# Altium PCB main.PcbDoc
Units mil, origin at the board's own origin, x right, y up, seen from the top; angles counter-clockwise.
Board outline 2845.7 x 1927.04 mil, 2 copper layers (Top Layer, Bottom Layer); 12 components, 7 nets, 37 pads, 138 vias.
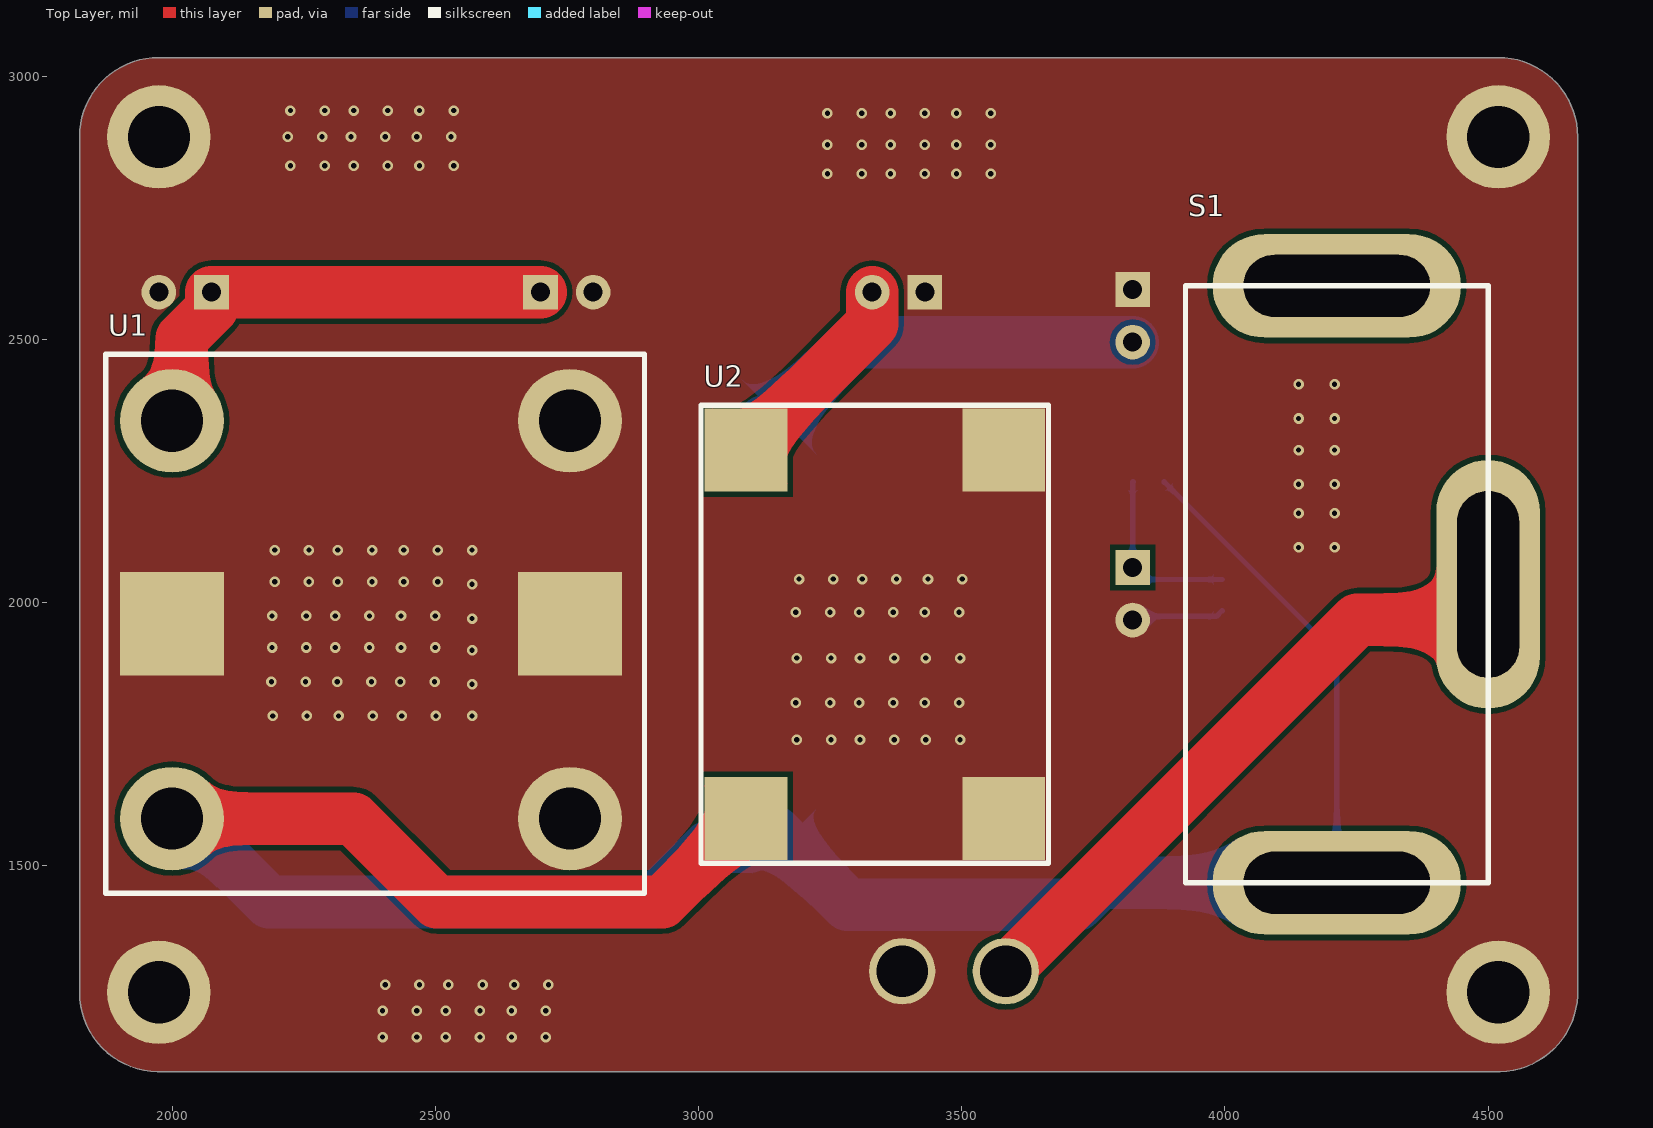
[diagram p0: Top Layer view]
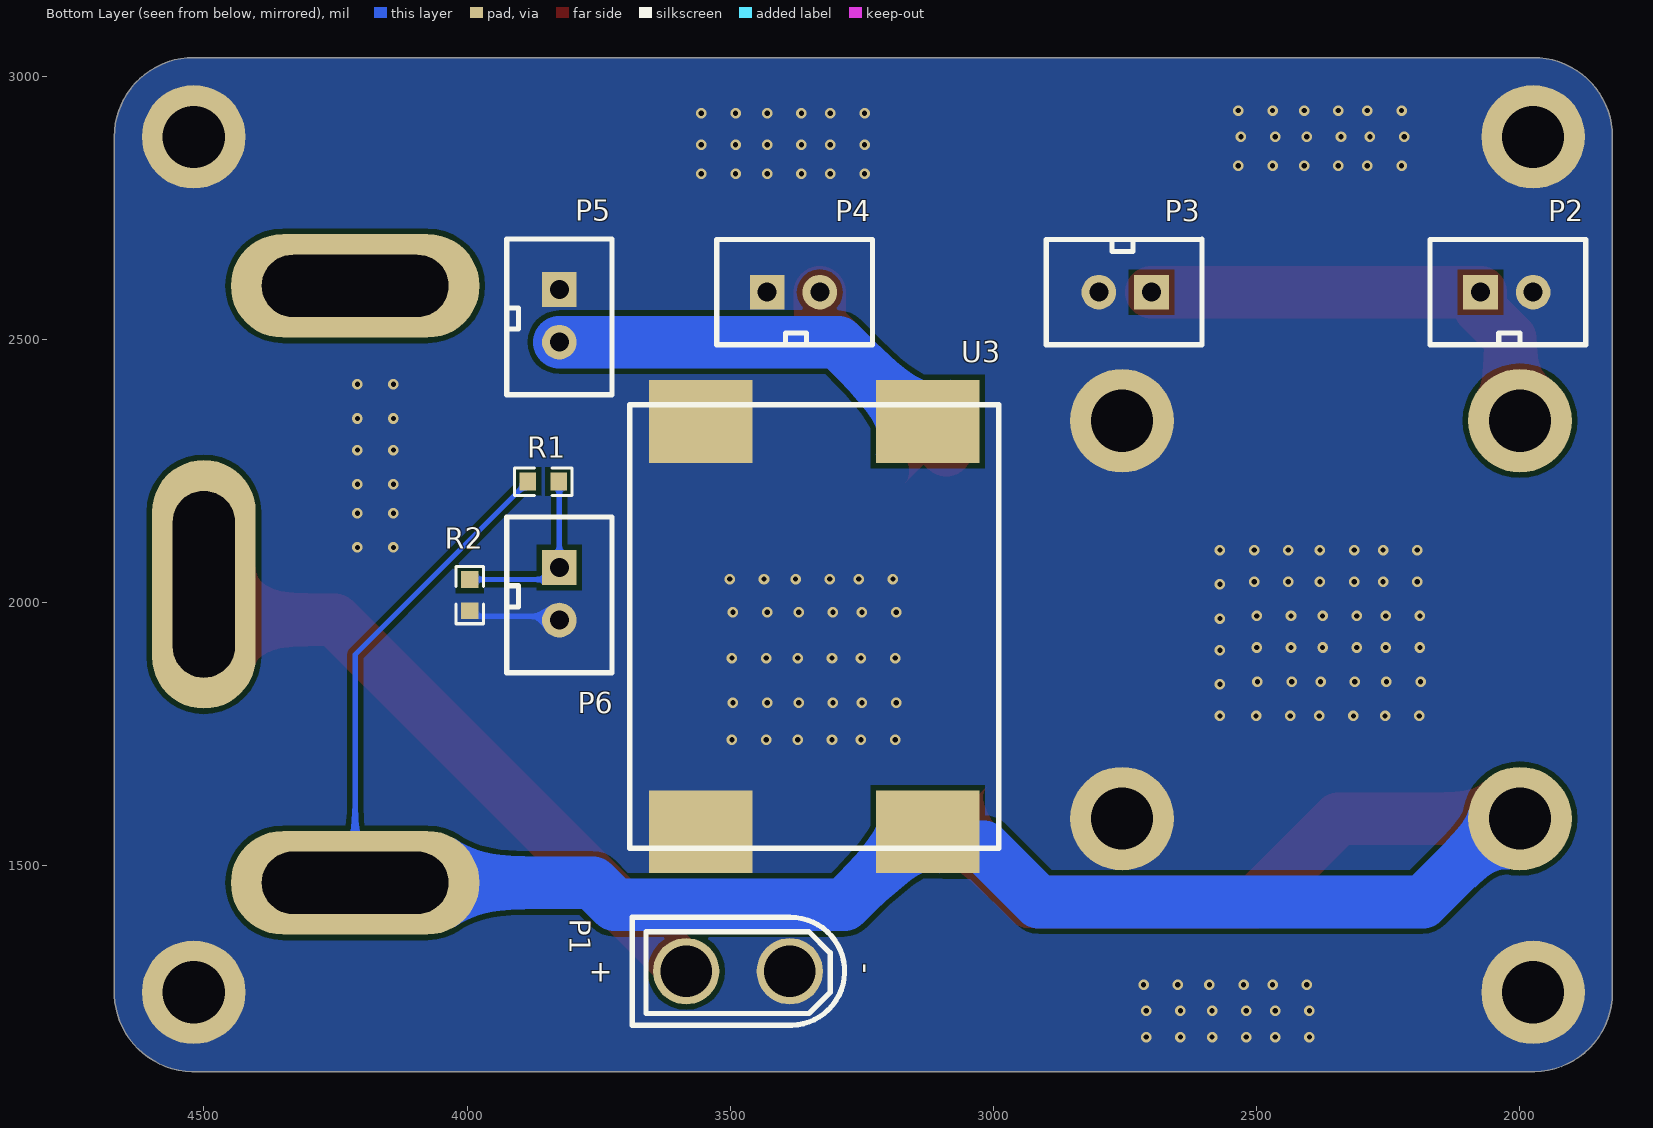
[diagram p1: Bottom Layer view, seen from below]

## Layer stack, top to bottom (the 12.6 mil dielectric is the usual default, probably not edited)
Top Solder: solder mask 0.4, Solder Resist, Dk 3.5
Top Layer: signal copper 1.4
Dielectric 1: dielectric 12.6, FR-4, Dk 4.8
Bottom Layer: signal copper 1.4
Bottom Solder: solder mask 0.4, Solder Resist, Dk 3.5

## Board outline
1824.32,1260 cw(c1829.33,1260) 1824.98,1262.5 1824.98,2882.5 cw(c1829.33,2885) 1824.32,2885 cw(c1975,2885) 1975,3035.68 cw(c1975,3030.67) 1975.05,3035.68 4519.33,3035.68 cw(c4519.33,2885) 4670.02,2885 cw(c4665,2885) 4670.01,2884.95 4670.02,1260 cw(c4665,1260) 4670.02,1260 cw(c4519.33,1260) 4670.02,1259.98 4670.02,1255 cw(c4665,1255) 4669.89,1253.89 cw(c4519.33,1260) 4522.99,1109.36 cw(c4520.41,1113.66) 4520.41,1108.65 1975,1108.65 cw(c1975,1113.67) 1972.47,1109.34 cw(c1975,1260)

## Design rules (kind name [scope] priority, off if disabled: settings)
Clearance [All] p1: gap=10 ignorepadtopadclearanceinfootprint=FALSE except(0: Arc-Hole Track-Hole SMDPad-Hole THPad-Hole Via-Hole Fill-Hole Poly-Hole Region-Hole Text-Hole)
PolygonConnect [All] p1: connectstyle=Direct reliefconductorwidth=10 reliefentries=4 polygonreliefangle="90 Angle" airgapwidth=10
RoutingVias [All] p1: holewidth=28 width=50 viastyle="Through Hole" minholewidth=28 minwidth=50 maxholewidth=28 maxwidth=50
SolderMaskExpansion [All] p1: expansion=4
Width [All] p1: maxlimit=100 minlimit=10 preferedwidth=60
30 further rules are at their usual default settings.

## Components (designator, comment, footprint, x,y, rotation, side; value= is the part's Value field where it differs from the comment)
P1 "Header 2" CONN-TH_XT30UPB-M 3465,1300 r0 bottom
P2 "Header 2" XH2.54-2A 2022.95,2589.8 r180 bottom
P3 "Header 2" XH2.54-2A 2752.05,2590.2 r0 bottom
P4 "Header 2" XH2.54-2A 3377.95,2589.8 r180 bottom
P5 "Header 2" XH2.54-2A 3825,2542.95 r270 bottom
P6 "Header 2" XH2.54-2A 3825,2015 r270 bottom
R1 "Res1" R0603 3819.33,2224.13 r0 bottom value=300K
R2 "Res1" R0603 4000.87,1978.64 r90 bottom value=100K
S1 "SW-SPDT" switch 4500,2601.93 r270 top
U1 "5V" 5V_8A 2000,2345.83 r0 top
U2 "7.4V" 7_4V 3005,2375 r0 top
U3 "9V" PCBComponent_1 3690.94,2376.02 r180 bottom

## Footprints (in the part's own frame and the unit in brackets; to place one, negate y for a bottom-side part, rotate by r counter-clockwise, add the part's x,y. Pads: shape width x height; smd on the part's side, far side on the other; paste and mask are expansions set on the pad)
5V_8A [mm]
  round 5 hole 3: 0(0,-19.2) 1(19.2,-19.2) 2(0,0) 3(19.2,0)
  rect 5x5 smd: 4(0,-9.8) 5(19.2,-9.8)
  silkscreen extent -3.2,-22.8 22.8,3.2
7_4V [mm]
  rect 4x4 smd: 0(2.159,-19.939) 1(14.605,-19.939) 2(2.159,-2.159) 3(14.605,-2.159)
  silkscreen extent 0,-22.1 16.76,0
CONN-TH_XT30UPB-M [mm]
  round 3.2 hole 2.5: 1(-1.982,0) 2(3.018,0)
  silkscreen extent -4.63,-2.6 5.62,2.6
PCBComponent_1 [mm]
  rect 5x4 smd: 0(14.375,-20.6) 1(3.425,-20.6) 2(14.375,-0.8) 3(3.425,-0.8)
  silkscreen extent 0,-21.4 17.8,0
R0603 [mil]
  rect 31.75x34.02 smd: 1(6.36,-5.87) 2(65.67,-5.87)
  silkscreen extent -19,-32 91,20
switch [mm]
  oval 5x12 hole 3 slot 9 at 90 deg: 1(0,-7.3) 3(28.8,-7.3)
  oval 12x5 hole 3 slot 9 at 0 deg: 2(14.4,0)
  silkscreen extent 0,-14.6 28.8,0
XH2.54-2A [mil]
  rect 66x66 hole 36: 1(-52.05,0.2)
  round 66 hole 36: 2(47.95,0.2)
  silkscreen extent -148,-100 148,100

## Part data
P1 P2 P3 P4 P5 P6: "Header, 2-Pin"
R1 R2: "Resistor"
S1: "SPDT Subminiature Toggle Switch, Right Angle Mounting, Vertical Actuation"
U1: library part 5V_8A
U2: library part 7_4V

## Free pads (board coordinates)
  round 196.85 hole 118.11: 0(1975,2885) 1(4519.33,2885) 2(1975,1260) 3(4519.33,1260)

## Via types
v1: diameter 20, hole 10, Top Layer to Bottom Layer, 138 vias

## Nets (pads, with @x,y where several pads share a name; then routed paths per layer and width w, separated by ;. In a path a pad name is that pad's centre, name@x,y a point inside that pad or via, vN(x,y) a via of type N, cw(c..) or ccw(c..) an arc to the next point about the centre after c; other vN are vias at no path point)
5V: P2.1 P3.1 U1.2 | length 900.2
  Top Layer w100: U1.2 2018.53,2364.36 2018.53,2502.01 2075,2558.48 P2.1 P3.1
7V4: P4.2 U2.2 | length 399.4
  Top Layer w100: U2.2 3330,2530 P4.2
9V: P5.2 U3.2 | length 762.1
  Bottom Layer w100: U3.2 3144.68,2344.53 3295.16,2495 P5.2
12V: R1.2 S1.3 U1.0 U2.0 U3.0 | length 4527.2
  Top Layer w100: U1.0 2344.65,1589.92 2503.08,1431.5 2931.5,1431.5 U2.0
  Bottom Layer w10: R1.2 3885,2228.87 4212.6,1901.27 S1.3
  Bottom Layer w100: U1.0 2026.21,1589.92 2184.63,1431.5 2914.33,1431.5 3019.09,1536.26 3096.26,1536.26 U3.0 3144.68,1565 3283.43,1426.26 3719.8,1426.26 3761.62,1468.07 S1.3
12V_IN: P1.2 S1.2 | length 1233.8
  Top Layer w100: P1.2 4251.57,1967.76 4455.26,1967.76 4500,2012.5 S1.2
GND: P1.1 P2.2 P3.2 P4.1 P5.1 P6.2 pad.0 pad.1 pad.2 pad.3 R2.1 U1.1 U1.3 U1.4 U1.5 U2.1 U2.3 U3.1 U3.3 | length 177.6
  Bottom Layer w10: P6.2 3831.87,1974.12 3984.12,1974.12 R2.1
  other v1: 2400,1175 2465,1175 2520,1175 2585,1175 2645,1175 2710,1175 2400,1225 2465,1225 2520,1225 2585,1225 2645,1225 2710,1225 2405,1274.24 2470,1274.24 2525,1274.24 2590,1274.24 2650,1274.24 2715,1274.24 3186.87,1740 3251.87,1740 3306.87,1740 3371.87,1740 3431.87,1740 3496.87,1740 2191.35,1785 2256.35,1785 2316.35,1785 2381.35,1785 2436.35,1785 2501.35,1785 2570,1785 3185,1810 3250,1810 3305,1810 3370,1810 3430,1810 3495,1810 2570,1845 2188.76,1850 2253.76,1850 2313.76,1850 2378.76,1850 2433.76,1850 2498.76,1850 3186.87,1895 3251.87,1895 3306.87,1895 3371.87,1895 3431.87,1895 3496.87,1895 2570,1910 2190,1915 2255,1915 2310,1915 2375,1915 2435,1915 2500,1915 2570,1970 2190,1975 2255,1975 2310,1975 2375,1975 2435,1975 2500,1975 3185,1982.05 3250,1982.05 3305,1982.05 3370,1982.05 3430,1982.05 3495,1982.05 2570,2035 2195,2040 2260,2040 2315,2040 2380,2040 2440,2040 2505,2040 3191.05,2045 3256.05,2045 3311.05,2045 3376.05,2045 3436.05,2045 3501.05,2045 2195,2100 2260,2100 2315,2100 2380,2100 2440,2100 2505,2100 2570,2100 4140,2105 4208.41,2105 4140,2170 4208.41,2170 4140,2225 4208.41,2225 4140,2290 4208.41,2290 4140,2350 4208.41,2350 4140,2415 4208.41,2415 3245,2815 3310,2815 3365,2815 3430,2815 3490,2815 3555,2815 2225,2830 2290,2830 2345,2830 2410,2830 2470,2830 2535,2830 3245,2870 3310,2870 3365,2870 3430,2870 3490,2870 3555,2870 2220,2885 2285,2885 2340,2885 2405,2885 2465,2885 2530,2885 3245,2930 3310,2930 3365,2930 3430,2930 3490,2930 3555,2930 2225,2935 2290,2935 2345,2935 2410,2935 2470,2935 2535,2935
NetP6_1: P6.1 R1.1 R2.2 | length 342.9
  Bottom Layer w10: R1.1 3824.8,2229.11 P6.1 3847.54,2044.31 R2.2
pads on no net: S1.1

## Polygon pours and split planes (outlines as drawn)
GND on Top Layer "GND_L01_P000" (solid, remove dead copper, pour order 0): 1824.32,1260 cw(c1829.33,1260) 1824.98,1262.5 1824.98,2882.5 cw(c1829.33,2885) 1824.32,2885 cw(c1975,2885) 1975,3035.68 cw(c1975,3030.67) 1975.05,3035.68 4519.33,3035.68 cw(c4519.33,2885) 4670.02,2885 cw(c4665,2885) 4670.01,2884.95 4670.02,1260 cw(c4665,1260) 4670.02,1260 cw(c4519.33,1260) 4670.02,1259.98 4670.02,1255 cw(c4665,1255) 4669.89,1253.89 cw(c4519.33,1260) 4522.99,1109.36 cw(c4520.41,1113.66) 4520.41,1108.65 1975,1108.65 cw(c1975,1113.67) 1972.47,1109.34 cw(c1975,1260)
GND on Bottom Layer "GND_L02_P002" (solid, remove dead copper, pour order 2): 1824.32,1260 cw(c1829.33,1260) 1824.98,1262.5 1824.98,2882.5 cw(c1829.33,2885) 1824.32,2885 cw(c1975,2885) 1975,3035.68 cw(c1975,3030.67) 1975.05,3035.68 4519.33,3035.68 cw(c4519.33,2885) 4670.02,2885 cw(c4665,2885) 4670.01,2884.95 4670.02,1260 cw(c4665,1260) 4670.02,1260 cw(c4519.33,1260) 4670.02,1259.98 4670.02,1255 cw(c4665,1255) 4669.89,1253.89 cw(c4519.33,1260) 4522.99,1109.36 cw(c4520.41,1113.66) 4520.41,1108.65 1975,1108.65 cw(c1975,1113.67) 1972.47,1109.34 cw(c1975,1260)

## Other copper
Bottom Layer:
  region: 3080,2305
  region: 4225,1480

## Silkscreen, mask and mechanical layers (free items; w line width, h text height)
Mechanical 1:
  lines w10: 4519.33,3035.68 cw(c4519.33,2885) 4670.02,2885 cw(c4665,2885) 4670.01,2884.95 4670.02,1260 ; 4519.33,3035.68 4519.33,3035.68 ; 4519.33,3035.68 1975.05,3035.68 ccw(c1975,3030.67) 1975,3035.68 ccw(c1975,2885) 1824.32,2885 ccw(c1829.33,2885) 1824.98,2882.5 1824.98,1262.5 ccw(c1829.33,1260) 1824.32,1260 ccw(c1975,1260) 1972.47,1109.34 ccw(c1975,1113.67) 1975,1108.65 4520.41,1108.65 ccw(c4520.41,1113.66) 4522.99,1109.36 ccw(c4519.33,1260) 4669.89,1253.89 ; 4669.89,1253.89 ccw(c4665,1255) 4670.02,1255 4670.02,1259.98 ; 4669.89,1253.89 4669.89,1253.89 ; 4670.01,1259.98 ccw(c4519.33,1260) 4670.02,1260 ; 4670.02,1260 ccw(c4665,1260) 4670.01,1260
